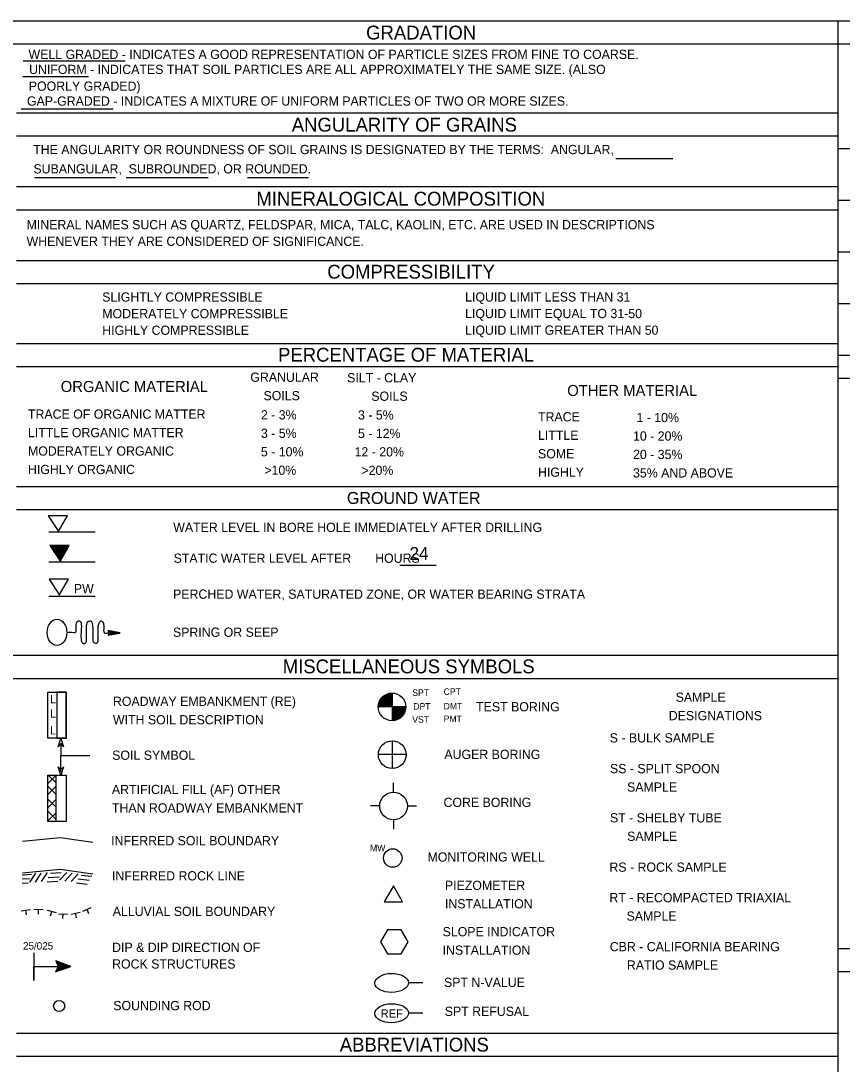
# Model space of a CAD drawing. Extents: x 278710 to 279187, y 171464 to 171625.
# Drawn here: x 279043.27 to 279081.88, y 171516.98 to 171566.02 of the extents above; entities that cross this region are included whole.
import ezdxf

# ---------------------------------------------------------------- set-up
doc = ezdxf.new("R2010")
doc.units = 0
doc.layers.add('Geotech Sheets and Borders Cell', color=7, linetype='Continuous')

msp = doc.modelspace()

# ---------------------------------------------------------------- linework, layer by layer
at = {"layer": 'Geotech Sheets and Borders Cell'}
for p, q in [((279005.33, 171566.02), (279158.027, 171566.02)), ((279081.678, 171566.02), (279081.678, 171485.806)), ((279005.33, 171564.936), (279158.027, 171564.936)), ((279043.374, 171564.138), (279048.18, 171564.138)), ((279043.357, 171563.4), (279046.445, 171563.4)), ((279043.287, 171561.882), (279047.616, 171561.882)), ((279081.678, 171561.682), (279043.07, 171561.682)), ((279081.678, 171560.598), (279043.07, 171560.598)), ((279121.332, 171560.012), (279081.678, 171560.012)), ((279071.241, 171559.557), (279073.916, 171559.557)), ((279043.914, 171558.659), (279047.726, 171558.659)), ((279048.219, 171558.663), (279052.076, 171558.663)), ((279053.933, 171558.659), (279056.796, 171558.659)), ((279081.678, 171558.212), (279043.07, 171558.212)), ((279121.332, 171557.583), (279081.678, 171557.583)), ((279081.678, 171557.127), (279043.07, 171557.127)), ((279121.332, 171555.154), (279081.678, 171555.154)), ((279081.678, 171554.741), (279043.07, 171554.741)), ((279081.678, 171553.657), (279043.07, 171553.657)), ((279121.332, 171552.724), (279081.678, 171552.724)), ((279081.678, 171550.837), (279043.07, 171550.837)), ((279121.332, 171550.295), (279081.678, 171550.295)), ((279081.678, 171549.753), (279043.07, 171549.753)), ((279121.332, 171549.21), (279081.678, 171549.21)), ((279081.678, 171544.113), (279043.07, 171544.113)), ((279079.076, 171544.113), (279043.07, 171544.113)), ((279081.678, 171543.029), (279043.07, 171543.029)), ((279044.589, 171542.005), (279046.758, 171542.005)), ((279044.589, 171540.587), (279046.758, 171540.587)), ((279061.09, 171540.435), (279062.794, 171540.435)), ((279044.589, 171538.973), (279046.758, 171538.973)), ((279047.938, 171537.251), (279047.365, 171537.359)), ((279047.365, 171537.359), (279047.426, 171537.255)), ((279047.426, 171537.255), (279047.374, 171537.142)), ((279047.374, 171537.142), (279047.924, 171537.246)), ((279047.413, 171537.233), (279047.664, 171537.281)), ((279047.413, 171537.233), (279047.664, 171537.281)), ((279047.413, 171537.229), (279047.664, 171537.277)), ((279047.413, 171537.225), (279047.664, 171537.272)), ((279047.413, 171537.22), (279047.664, 171537.268)), ((279047.413, 171537.216), (279047.664, 171537.264)), ((279047.413, 171537.216), (279047.664, 171537.264)), ((279047.417, 171537.212), (279047.669, 171537.259)), ((279047.417, 171537.207), (279047.669, 171537.255)), ((279047.417, 171537.203), (279047.669, 171537.251)), ((279047.417, 171537.199), (279047.669, 171537.246)), ((279047.417, 171537.194), (279047.669, 171537.242)), ((279047.417, 171537.19), (279047.669, 171537.238)), ((279047.417, 171537.19), (279047.669, 171537.238)), ((279047.421, 171537.272), (279047.677, 171537.229)), ((279047.421, 171537.272), (279047.677, 171537.229)), ((279047.421, 171537.268), (279047.677, 171537.225)), ((279047.421, 171537.186), (279047.673, 171537.233)), ((279047.421, 171537.181), (279047.673, 171537.229)), ((279047.421, 171537.177), (279047.673, 171537.225)), ((279047.426, 171537.303), (279047.682, 171537.259)), ((279047.426, 171537.298), (279047.682, 171537.255)), ((279047.426, 171537.294), (279047.682, 171537.251)), ((279047.426, 171537.29), (279047.682, 171537.246)), ((279047.426, 171537.285), (279047.682, 171537.242)), ((279047.426, 171537.281), (279047.682, 171537.238)), ((279047.43, 171537.324), (279047.686, 171537.281)), ((279047.43, 171537.316), (279047.686, 171537.272)), ((279047.43, 171537.311), (279047.686, 171537.268)), ((279047.43, 171537.307), (279047.686, 171537.264)), ((279047.434, 171537.329), (279047.69, 171537.285)), ((279047.439, 171537.337), (279047.907, 171537.251)), ((279047.421, 171537.173), (279047.673, 171537.22)), ((279047.421, 171537.173), (279047.673, 171537.22)), ((279047.421, 171537.168), (279047.673, 171537.216)), ((279047.426, 171537.164), (279047.677, 171537.212)), ((279081.678, 171536.183), (279005.33, 171536.183)), ((279081.678, 171535.099), (279005.33, 171535.099)), ((279044.966, 171534.466), (279044.966, 171532.297)), ((279060.722, 171534.426), (279060.722, 171533.125)), ((279061.372, 171533.775), (279060.071, 171533.775)), ((279060.73, 171532.179), (279060.73, 171530.878)), ((279061.381, 171531.528), (279060.08, 171531.528)), ((279044.537, 171530.175), (279044.91, 171530.548)), ((279044.91, 171530.214), (279044.558, 171530.566)), ((279044.918, 171530.535), (279044.918, 171528.384)), ((279044.528, 171529.646), (279044.918, 171530.037)), ((279044.892, 171529.685), (279044.537, 171530.041)), ((279060.791, 171529.767), (279060.791, 171530.201)), ((279044.537, 171529.034), (279044.918, 171529.416)), ((279044.892, 171529.091), (279044.545, 171529.438)), ((279060.14, 171529.116), (279059.706, 171529.116)), ((279061.442, 171529.116), (279061.876, 171529.116)), ((279044.541, 171528.418), (279044.923, 171528.8)), ((279044.914, 171528.497), (279044.545, 171528.865)), ((279060.791, 171528.466), (279060.791, 171528.032)), ((279043.699, 171525.538), (279043.973, 171525.954)), ((279043.96, 171525.542), (279044.229, 171525.959)), ((279044.246, 171525.573), (279044.515, 171525.989)), ((279044.662, 171525.954), (279045.157, 171525.985)), ((279045.087, 171525.629), (279045.426, 171525.993)), ((279045.335, 171525.586), (279045.677, 171525.954)), ((279043.335, 171525.876), (279043.773, 171525.907)), ((279043.335, 171525.685), (279043.682, 171525.707)), ((279043.335, 171525.482), (279043.621, 171525.499)), ((279044.506, 171525.547), (279045.009, 171525.577)), ((279044.558, 171525.751), (279045.066, 171525.785)), ((279045.634, 171525.564), (279045.964, 171525.928)), ((279045.881, 171525.499), (279046.38, 171525.434)), ((279045.964, 171525.685), (279046.476, 171525.629)), ((279046.107, 171525.868), (279046.601, 171525.811)), ((279043.287, 171524.193), (279043.717, 171524.254)), ((279043.534, 171524.007), (279043.504, 171524.224)), ((279043.886, 171524.258), (279044.32, 171524.245)), ((279044.098, 171524.037), (279044.103, 171524.25)), ((279044.506, 171524.215), (279044.927, 171524.106)), ((279044.662, 171523.95), (279044.719, 171524.163)), ((279045.035, 171524.054), (279045.469, 171524.033)), ((279045.244, 171523.829), (279045.252, 171524.041)), ((279045.63, 171524.028), (279046.055, 171524.119)), ((279045.886, 171523.864), (279045.842, 171524.076)), ((279046.181, 171524.167), (279046.58, 171524.341)), ((279046.467, 171524.054), (279046.38, 171524.254)), ((279081.678, 171522.419), (279121.332, 171522.419)), ((279081.678, 171521.334), (279121.332, 171521.334)), ((279061.489, 171520.814), (279062.175, 171520.814)), ((279061.489, 171519.391), (279062.175, 171519.391)), ((279043.07, 171518.437), (279081.678, 171518.437)), ((279043.07, 171517.352), (279081.678, 171517.352))]:
    msp.add_line(p, q, dxfattribs=at)
for points in [[(279045.027, 171541.996), (279045.461, 171542.747), (279044.55, 171542.747), (279045.048, 171541.996)], [(279045.113, 171540.613), (279045.547, 171541.363), (279044.636, 171541.363), (279045.135, 171540.613)], [(279044.68, 171541.337), (279045.517, 171541.337), (279045.122, 171540.669), (279044.68, 171541.337)], [(279044.727, 171541.311), (279045.478, 171541.311), (279045.122, 171540.708), (279044.736, 171541.289), (279045.452, 171541.289), (279045.122, 171540.747), (279044.771, 171541.268), (279045.413, 171541.268), (279045.122, 171540.795), (279044.818, 171541.242), (279045.369, 171541.242), (279045.118, 171540.842), (279044.858, 171541.216), (279045.326, 171541.211), (279045.113, 171540.886), (279044.901, 171541.19), (279045.291, 171541.19), (279045.113, 171540.925), (279044.944, 171541.168), (279045.252, 171541.168), (279045.113, 171540.973), (279044.988, 171541.15), (279045.218, 171541.15), (279045.118, 171541.012), (279045.035, 171541.129), (279045.174, 171541.129), (279045.113, 171541.033), (279045.074, 171541.107), (279045.144, 171541.111), (279045.113, 171541.077)], [(279045.07, 171539.021), (279045.504, 171539.771), (279044.593, 171539.771), (279045.092, 171539.021)], [(279047.374, 171537.355), (279047.434, 171537.251), (279047.434, 171537.342), (279047.378, 171537.355), (279047.43, 171537.268), (279047.43, 171537.337), (279047.387, 171537.346), (279047.426, 171537.281), (279047.426, 171537.333), (279047.395, 171537.337), (279047.421, 171537.303), (279047.421, 171537.294), (279047.421, 171537.324), (279047.404, 171537.329), (279047.421, 171537.329), (279047.413, 171537.316), (279047.439, 171537.246), (279047.43, 171537.246), (279047.426, 171537.242), (279047.382, 171537.146), (279047.426, 171537.155), (279047.439, 171537.246), (279047.43, 171537.238), (279047.391, 171537.151), (279047.421, 171537.159), (279047.43, 171537.233), (279047.4, 171537.155), (279047.417, 171537.164), (279047.421, 171537.207), (279047.408, 171537.159), (279047.434, 171537.159), (279047.916, 171537.251)], [(279047.69, 171537.281), (279047.89, 171537.251), (279047.682, 171537.212), (279047.69, 171537.277), (279047.864, 171537.251), (279047.686, 171537.22), (279047.695, 171537.268), (279047.838, 171537.246), (279047.816, 171537.255), (279047.69, 171537.272), (279047.69, 171537.225), (279047.825, 171537.246), (279047.695, 171537.264), (279047.69, 171537.233), (279047.803, 171537.246), (279047.695, 171537.259), (279047.699, 171537.238), (279047.781, 171537.251), (279047.695, 171537.255), (279047.695, 171537.238), (279047.751, 171537.255), (279047.699, 171537.246), (279047.695, 171537.229), (279047.755, 171537.238), (279047.699, 171537.285), (279047.781, 171537.268), (279047.69, 171537.285), (279047.434, 171537.255), (279047.46, 171537.246), (279047.469, 171537.251), (279047.469, 171537.255), (279047.491, 171537.255), (279047.491, 171537.259), (279047.447, 171537.32), (279047.53, 171537.303), (279047.525, 171537.316), (279047.439, 171537.333)], [(279047.439, 171537.259), (279047.478, 171537.251), (279047.434, 171537.242), (279047.538, 171537.264), (279047.439, 171537.272), (279047.525, 171537.255), (279047.504, 171537.272), (279047.434, 171537.324), (279047.63, 171537.285), (279047.686, 171537.277), (279047.682, 171537.207), (279047.673, 171537.242)], [(279060.079, 171533.796), (279060.717, 171533.804), (279060.079, 171533.809), (279060.114, 171533.813), (279060.717, 171533.822), (279060.079, 171533.83), (279060.713, 171533.843), (279060.088, 171533.848), (279060.713, 171533.861), (279060.084, 171533.874), (279060.717, 171533.882), (279060.097, 171533.895), (279060.717, 171533.908), (279060.101, 171533.921), (279060.713, 171533.934), (279060.101, 171533.947), (279060.717, 171533.952), (279060.118, 171533.973), (279060.717, 171533.973), (279060.123, 171533.995), (279060.717, 171533.995), (279060.131, 171534.021), (279060.721, 171534.017), (279060.149, 171534.047), (279060.717, 171534.043), (279060.162, 171534.078), (279060.721, 171534.065), (279060.188, 171534.108), (279060.721, 171534.095), (279060.201, 171534.134), (279060.717, 171534.121), (279060.227, 171534.164), (279060.717, 171534.156), (279060.253, 171534.195), (279060.717, 171534.182), (279060.279, 171534.225), (279060.726, 171534.208), (279060.318, 171534.26), (279060.717, 171534.242), (279060.361, 171534.29), (279060.717, 171534.277), (279060.418, 171534.32), (279060.717, 171534.312), (279060.491, 171534.355), (279060.713, 171534.346), (279060.582, 171534.373), (279060.717, 171534.381), (279060.652, 171534.394)], [(279061.36, 171533.759), (279060.722, 171533.75), (279061.36, 171533.746), (279061.325, 171533.741), (279060.722, 171533.733), (279061.36, 171533.724), (279060.726, 171533.711), (279061.351, 171533.706), (279060.726, 171533.693), (279061.355, 171533.68), (279060.722, 171533.672), (279061.342, 171533.659), (279060.722, 171533.646), (279061.338, 171533.633), (279060.726, 171533.62), (279061.338, 171533.607), (279060.722, 171533.602), (279061.321, 171533.581), (279060.722, 171533.581), (279061.316, 171533.559), (279060.722, 171533.559), (279061.308, 171533.533), (279060.718, 171533.537), (279061.29, 171533.507), (279060.722, 171533.511), (279061.277, 171533.477), (279060.718, 171533.49), (279061.251, 171533.446), (279060.718, 171533.459), (279061.238, 171533.42), (279060.722, 171533.433), (279061.212, 171533.39), (279060.722, 171533.398), (279061.186, 171533.359), (279060.722, 171533.372), (279061.16, 171533.329), (279060.713, 171533.346), (279061.121, 171533.294), (279060.722, 171533.312), (279061.078, 171533.264), (279060.722, 171533.277), (279061.021, 171533.234), (279060.722, 171533.242), (279060.948, 171533.199), (279060.726, 171533.208), (279060.856, 171533.182), (279060.722, 171533.173), (279060.787, 171533.16)], [(279045.148, 171532.071), (279045.148, 171531.49), (279046.511, 171531.49)], [(279045.148, 171530.726), (279045.148, 171531.494)], [(279043.344, 171527.46), (279045.122, 171527.629), (279046.658, 171527.421)], [(279043.339, 171525.972), (279045.118, 171526.141), (279046.653, 171525.933)], [(279060.353, 171524.614), (279061.22, 171524.614), (279060.787, 171525.364), (279060.353, 171524.614)], [(279060.505, 171522.172), (279061.155, 171522.172), (279061.481, 171522.736), (279061.155, 171523.3), (279060.505, 171523.3), (279060.179, 171522.736), (279060.505, 171522.172)], [(279043.881, 171522.219), (279043.881, 171520.918), (279043.881, 171521.569), (279045.617, 171521.569), (279044.91, 171521.842), (279045.018, 171521.569), (279044.914, 171521.343), (279044.901, 171521.317), (279045.608, 171521.564), (279045.035, 171521.556), (279044.927, 171521.334), (279045.543, 171521.547), (279045.166, 171521.547), (279045.04, 171521.543), (279044.949, 171521.356), (279045.482, 171521.538), (279045.053, 171521.538), (279044.979, 171521.378), (279045.443, 171521.538), (279045.014, 171521.521), (279045.066, 171521.512), (279044.992, 171521.387), (279045.07, 171521.538), (279045.391, 171521.521), (279045.018, 171521.4), (279045.087, 171521.517), (279045.348, 171521.517), (279045.044, 171521.426), (279045.092, 171521.508), (279045.278, 171521.508), (279045.074, 171521.443), (279045.096, 171521.504), (279045.209, 171521.504), (279045.1, 171521.465), (279045.113, 171521.491), (279045.166, 171521.486), (279045.126, 171521.478), (279045.04, 171521.439), (279045.066, 171521.495), (279045.018, 171521.404), (279044.966, 171521.378), (279045.035, 171521.521), (279044.988, 171521.69), (279044.931, 171521.816), (279045.569, 171521.577), (279045.027, 171521.586), (279045.526, 171521.595), (279044.957, 171521.799), (279045.035, 171521.577), (279045.456, 171521.599), (279045.044, 171521.599), (279044.983, 171521.777), (279045.014, 171521.755), (279045.044, 171521.612), (279045.031, 171521.755), (279045.465, 171521.603), (279045.057, 171521.612), (279045.04, 171521.729), (279045.404, 171521.621), (279045.066, 171521.625), (279045.352, 171521.625), (279045.053, 171521.716), (279045.3, 171521.625), (279045.044, 171521.699), (279045.07, 171521.642), (279045.244, 171521.621), (279045.109, 171521.651), (279045.053, 171521.647), (279045.061, 171521.673), (279045.248, 171521.638), (279045.07, 171521.682), (279045.035, 171521.751), (279045.222, 171521.677), (279044.983, 171521.773), (279045.044, 171521.703), (279045.001, 171521.747), (279045.018, 171521.716), (279045.027, 171521.695)]]:
    msp.add_lwpolyline(points, dxfattribs=at)
for points in [[(279044.532, 171534.466), (279045.4, 171534.466), (279045.4, 171532.297), (279044.532, 171532.297)], [(279044.966, 171532.297), (279045.4, 171532.297), (279045.4, 171534.466), (279044.966, 171534.466)], [(279045.018, 171531.902), (279045.148, 171532.292), (279045.278, 171531.902), (279045.148, 171532.032)], [(279045.278, 171530.956), (279045.148, 171530.566), (279045.018, 171530.956), (279045.148, 171530.826)], [(279044.532, 171530.561), (279045.4, 171530.561), (279045.4, 171528.392), (279044.532, 171528.392)]]:
    msp.add_lwpolyline(points, close=True, dxfattribs=at)
for centre, radius in [((279060.722, 171533.775), 0.651), ((279060.73, 171531.528), 0.651), ((279060.791, 171529.116), 0.651), ((279060.756, 171526.67), 0.434), ((279045.07, 171519.712), 0.26)]:
    msp.add_circle(centre, radius, dxfattribs=at)
for centre, major_axis, ratio in [((279044.969, 171537.276), (0, -0.618), 0.743839), ((279060.702, 171520.798), (0.787, 0.011), 0.568627), ((279060.702, 171519.375), (0.787, 0.011), 0.568627)]:
    msp.add_ellipse(centre, major_axis=major_axis, ratio=ratio, dxfattribs=at)
msp.add_spline([(279045.43, 171537.277), (279045.76, 171537.272), (279045.829, 171537.272), (279045.873, 171537.481), (279045.873, 171537.676), (279045.894, 171537.736), (279045.925, 171537.789), (279046.046, 171537.81), (279046.111, 171537.663), (279046.098, 171537.251), (279046.098, 171537.003), (279046.111, 171536.878), (279046.172, 171536.778), (279046.263, 171536.756), (279046.298, 171536.765), (279046.358, 171536.899), (279046.358, 171537.042), (279046.358, 171537.467), (279046.358, 171537.602), (279046.38, 171537.706), (279046.411, 171537.789), (279046.463, 171537.797), (279046.523, 171537.819), (279046.575, 171537.797), (279046.606, 171537.736), (279046.649, 171537.498), (279046.649, 171537.077), (279046.649, 171536.96), (279046.666, 171536.825), (279046.732, 171536.778), (279046.814, 171536.765), (279046.875, 171536.795), (279046.905, 171536.878), (279046.905, 171537.003), (279046.905, 171537.489), (279046.905, 171537.58), (279046.935, 171537.684), (279046.966, 171537.736), (279047, 171537.789), (279047.031, 171537.819), (279047.07, 171537.81), (279047.122, 171537.767), (279047.152, 171537.697), (279047.165, 171537.615), (279047.165, 171537.428), (279047.165, 171537.324), (279047.226, 171537.242), (279047.361, 171537.251), (279047.608, 171537.251), (279047.938, 171537.251)], degree=3, dxfattribs=at)

# ---------------------------------------------------------------- texts
for s, height, p in [('GRADATION', 0.6507, (279059.503, 171565.144)), ('WELL GRADED - INDICATES A GOOD REPRESENTATION OF PARTICLE SIZES FROM FINE TO COARSE.', 0.43381, (279043.63, 171564.229)), ('UNIFORM - INDICATES THAT SOIL PARTICLES ARE ALL APPROXIMATELY THE SAME SIZE. (ALSO', 0.43381, (279043.656, 171563.522)), ('POORLY GRADED)', 0.43381, (279043.643, 171562.736)), ('GAP-GRADED - INDICATES A MIXTURE OF UNIFORM PARTICLES OF TWO OR MORE SIZES.', 0.43381, (279043.556, 171562.034)), ('ANGULARITY OF GRAINS', 0.6507, (279056.006, 171560.815)), ('THE ANGULARITY OR ROUNDNESS OF SOIL GRAINS IS DESIGNATED BY THE TERMS:  ANGULAR,', 0.43381, (279043.849, 171559.756)), ('SUBANGULAR,  SUBROUNDED, OR ROUNDED.', 0.43381, (279043.86, 171558.849)), ('MINERALOGICAL COMPOSITION', 0.6507, (279054.34, 171557.336)), ('MINERAL NAMES SUCH AS QUARTZ, FELDSPAR, MICA, TALC, KAOLIN, ETC. ARE USED IN DESCRIPTIONS ', 0.43381, (279043.539, 171556.225)), ('WHENEVER THEY ARE CONSIDERED OF SIGNIFICANCE.', 0.43381, (279043.539, 171555.444)), ('COMPRESSIBILITY', 0.6507, (279057.676, 171553.904)), ('SLIGHTLY COMPRESSIBLE', 0.43381, (279047.096, 171552.824)), ('LIQUID LIMIT LESS THAN 31', 0.43381, (279064.157, 171552.828)), ('MODERATELY COMPRESSIBLE', 0.43381, (279047.096, 171552.043)), ('LIQUID LIMIT EQUAL TO 31-50', 0.43381, (279064.157, 171552.047)), ('HIGHLY COMPRESSIBLE', 0.43381, (279047.096, 171551.262)), ('LIQUID LIMIT GREATER THAN 50', 0.43381, (279064.157, 171551.266)), ('PERCENTAGE OF MATERIAL', 0.6507, (279055.36, 171550)), ('GRANULAR', 0.4338, (279054.058, 171549.054)), ('ORGANIC MATERIAL', 0.52056, (279045.144, 171548.573)), ('SILT - CLAY', 0.43381, (279058.61, 171549.028)), (' SOILS', 0.4338, (279054.518, 171548.187)), ('SOILS', 0.4338, (279059.747, 171548.161)), ('OTHER MATERIAL', 0.52056, (279068.959, 171548.386)), ('TRACE OF ORGANIC MATTER', 0.43381, (279043.604, 171547.319)), ('2 - 3%', 0.4338, (279054.557, 171547.284)), (' 3 - 5%', 0.4338, (279058.96, 171547.28)), ('TRACE', 0.4338, (279067.584, 171547.193)), (' 1 - 10%', 0.4338, (279072.052, 171547.159)), ('LITTLE ORGANIC MATTER', 0.43381, (279043.604, 171546.451)), ('3 - 5%', 0.4338, (279054.557, 171546.417)), (' 5 - 12%', 0.4338, (279058.96, 171546.412)), ('LITTLE', 0.4338, (279067.584, 171546.326)), ('10 - 20%', 0.4338, (279072.052, 171546.291)), ('MODERATELY ORGANIC', 0.43381, (279043.604, 171545.584)), ('5 - 10%', 0.4338, (279054.557, 171545.549)), ('12 - 20%', 0.4338, (279058.96, 171545.545)), ('SOME', 0.4338, (279067.584, 171545.458)), ('20 - 35%', 0.4338, (279072.052, 171545.423)), ('HIGHLY ORGANIC', 0.43381, (279043.604, 171544.716)), (' >10%', 0.4338, (279054.557, 171544.682)), ('  >20%', 0.4338, (279058.96, 171544.677)), ('HIGHLY', 0.4338, (279067.584, 171544.59)), ('35% AND ABOVE', 0.43381, (279072.052, 171544.556)), ('GROUND WATER', 0.56395, (279058.6, 171543.311)), ('WATER LEVEL IN BORE HOLE IMMEDIATELY AFTER DRILLING', 0.43381, (279050.434, 171541.996)), ('24', 0.6, (279061.543, 171540.686)), ('STATIC WATER LEVEL AFTER       HOURS', 0.43381, (279050.451, 171540.547)), ('PW', 0.4338, (279045.76, 171539.116)), ('PERCHED WATER, SATURATED ZONE, OR WATER BEARING STRATA', 0.43381, (279050.426, 171538.856)), ('SPRING OR SEEP', 0.43381, (279050.42, 171537.068)), ('MISCELLANEOUS SYMBOLS', 0.6507, (279055.581, 171535.351)), ('L', 0.39, (279044.639, 171533.937)), ('SPT', 0.3037, (279061.672, 171534.292)), ('CPT', 0.3037, (279063.147, 171534.34)), ('  SAMPLE', 0.4338, (279073.733, 171534.014)), ('ROADWAY EMBANKMENT (RE)', 0.43381, (279047.599, 171533.819)), ('DPT', 0.3037, (279061.719, 171533.646)), ('DMT', 0.3037, (279063.147, 171533.659)), ('TEST BORING', 0.43381, (279064.674, 171533.563)), ('L', 0.39, (279044.639, 171533.269)), ('WITH SOIL DESCRIPTION', 0.43381, (279047.599, 171532.952)), ('VST', 0.3037, (279061.672, 171533.03)), ('PMT', 0.3037, (279063.147, 171533.064)), ('DESIGNATIONS', 0.43381, (279073.733, 171533.146)), ('L', 0.39, (279044.639, 171532.479)), ('S - BULK SAMPLE', 0.43381, (279070.956, 171532.101)), ('SOIL SYMBOL', 0.43381, (279047.564, 171531.286)), ('AUGER BORING', 0.43381, (279063.181, 171531.325)), ('SS - SPLIT SPOON', 0.43381, (279070.966, 171530.657)), ('ARTIFICIAL FILL (AF) OTHER', 0.43381, (279047.551, 171529.676)), ('     SAMPLE', 0.43381, (279070.966, 171529.79)), ('CORE BORING', 0.43381, (279063.142, 171529.069)), ('THAN ROADWAY EMBANKMENT', 0.43381, (279047.551, 171528.809)), ('ST - SHELBY TUBE', 0.43381, (279070.968, 171528.344)), ('     SAMPLE', 0.43381, (279070.968, 171527.477)), ('INFERRED SOIL BOUNDARY', 0.43381, (279047.515, 171527.269)), ('   MONITORING WELL', 0.43381, (279061.906, 171526.501)), ('RS - ROCK SAMPLE', 0.43381, (279070.941, 171526.024)), ('INFERRED ROCK LINE', 0.43381, (279047.556, 171525.616)), ('PIEZOMETER', 0.4338, (279063.207, 171525.169)), ('RT - RECOMPACTED TRIAXIAL', 0.43381, (279070.941, 171524.593)), ('INSTALLATION', 0.43381, (279063.207, 171524.302)), ('ALLUVIAL SOIL BOUNDARY', 0.43381, (279047.59, 171523.946)), ('     SAMPLE', 0.43381, (279070.941, 171523.726)), ('SLOPE INDICATOR', 0.43381, (279063.099, 171522.992)), ('25/025', 0.347, (279043.37, 171522.367)), ('DIP & DIP DIRECTION OF ', 0.43381, (279047.56, 171522.255)), ('INSTALLATION', 0.43381, (279063.099, 171522.124)), ('CBR - CALIFORNIA BEARING', 0.43381, (279070.957, 171522.288)), ('ROCK STRUCTURES', 0.43381, (279047.56, 171521.474)), ('     RATIO SAMPLE', 0.43381, (279070.957, 171521.421)), ('SPT N-VALUE', 0.43381, (279063.164, 171520.606)), ('SOUNDING ROD', 0.43381, (279047.615, 171519.517)), ('SPT REFUSAL', 0.43381, (279063.199, 171519.248)), ('REF', 0.3904, (279060.184, 171519.165)), ('ABBREVIATIONS', 0.6507, (279058.262, 171517.573))]:
    msp.add_text(s, height=height, dxfattribs=at).set_placement(p)
msp.add_text('MW', height=0.3037, rotation=360, dxfattribs=at).set_placement((279059.687, 171526.989))

doc.saveas('drawing.dxf')
